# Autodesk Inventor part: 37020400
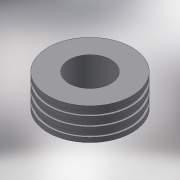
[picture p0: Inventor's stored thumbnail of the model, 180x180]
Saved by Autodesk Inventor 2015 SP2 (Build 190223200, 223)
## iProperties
Created: 2017-08
Part Number: 37020400
Material: Generic
Description: PLASSON MAN HOLE ADAPTOR 400
Document SubType Name: Modeling
Designer: Кирилл
Density: 1 g/cm^3
Appearance: Default
Author: Кирилл
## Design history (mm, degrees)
derived "37020-477207.ipt"
feature "Solid1::37020-477207.ipt"
tag "TaggingFeature1"
body "Solid1"
other parameters: "d0" = 135, "d2" = 532, "d3" = 353, "d6" = 59, "L_" = 135, "d_1" = 353, "H_" = 59
